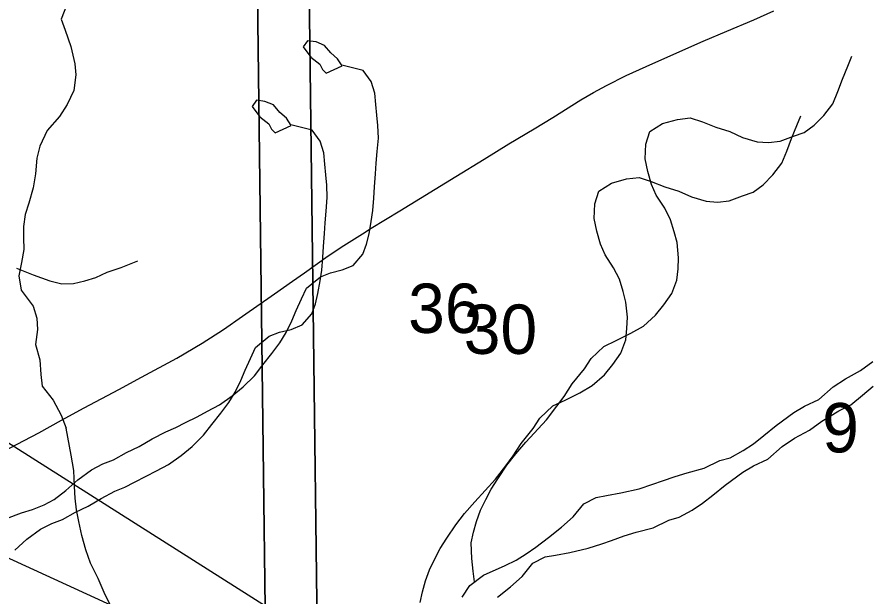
# Model space of a CAD drawing. Extents: x -21.1 to 50.3, y -4.9 to 22.1.
# Drawn here: x 4.587 to 5.308, y 17.38 to 17.871 of the extents above; entities that cross this region are included whole.
import ezdxf

# ---------------------------------------------------------------- set-up
doc = ezdxf.new("R2010")
doc.units = 0
for name, color, linetype in [('GM_X_Minor_Lake', 7, 'Continuous'), ('GM_X_Minor_River', 7, 'Continuous'), ('GM_X_Section', 7, 'Continuous'), ('GM_X_Section_Text', 7, 'Continuous'), ('GM_X_Township_Road', 7, 'Continuous'), ('SH_Data', 7, 'Continuous')]:
    doc.layers.add(name, color=color, linetype=linetype)

msp = doc.modelspace()

# ---------------------------------------------------------------- linework, layer by layer
at = {"layer": 'GM_X_Minor_Lake'}
for points in [[(4.86329, 17.82987), (4.85943, 17.8359), (4.85369, 17.84077), (4.84831, 17.84717), (4.84107, 17.85013), (4.83385, 17.85119), (4.83012, 17.84583), (4.83666, 17.83718), (4.84431, 17.83119), (4.84664, 17.82666), (4.84971, 17.82366)], [(4.84971, 17.82366), (4.86329, 17.82987)], [(4.82, 17.77936), (4.81614, 17.78539), (4.8104, 17.79026), (4.80502, 17.79665), (4.79778, 17.79961), (4.79056, 17.80067), (4.78683, 17.79532), (4.79337, 17.78666), (4.80102, 17.78067), (4.80335, 17.77614), (4.80642, 17.77314)], [(4.80642, 17.77314), (4.82, 17.77936)]]:
    msp.add_lwpolyline(points, dxfattribs=at)
at = {"layer": 'GM_X_Minor_River'}
for points in [[(4.63015, 17.88241), (4.62483, 17.86952), (4.62824, 17.86004), (4.63316, 17.84638), (4.63656, 17.83159), (4.63732, 17.82211), (4.63579, 17.80883), (4.6301, 17.79708), (4.62365, 17.78684), (4.61303, 17.77508), (4.60696, 17.7618), (4.6043, 17.75156), (4.60315, 17.73829), (4.60125, 17.72653), (4.59746, 17.71326), (4.59442, 17.70377), (4.5929, 17.69353), (4.59289, 17.68405), (4.59327, 17.67419), (4.59136, 17.66319), (4.58908, 17.65181), (4.59097, 17.63968), (4.6012, 17.62603), (4.60423, 17.61579), (4.60498, 17.6063), (4.60308, 17.59341), (4.60686, 17.58051), (4.60761, 17.568), (4.60875, 17.55814), (4.61822, 17.54638), (4.62504, 17.53349), (4.6292, 17.52249)], [(4.9756, 17.39228), (4.97444, 17.40135), (4.97323, 17.41198), (4.97278, 17.42528), (4.97463, 17.4344), (4.97724, 17.44354), (4.98062, 17.45305), (4.98513, 17.4622), (4.98965, 17.47096), (4.99531, 17.47973), (5.00286, 17.49116), (5.01042, 17.5007), (5.01912, 17.51063), (5.03652, 17.52972), (5.04521, 17.54116), (5.05164, 17.54955), (5.05843, 17.56023), (5.06863, 17.57282), (5.07429, 17.58159), (5.08527, 17.59191), (5.09552, 17.5969), (5.10805, 17.60305), (5.11868, 17.60919), (5.1289, 17.61836), (5.13608, 17.62714), (5.14288, 17.63667), (5.147, 17.64809), (5.14809, 17.65759), (5.14842, 17.66709), (5.14721, 17.68), (5.14487, 17.6891), (5.14177, 17.69934), (5.13676, 17.7092), (5.12947, 17.72017), (5.12561, 17.72927), (5.12251, 17.74026), (5.12016, 17.75089), (5.12085, 17.76343), (5.12422, 17.77408), (5.13484, 17.78098), (5.14776, 17.78447), (5.15841, 17.78567), (5.16871, 17.7823), (5.18015, 17.77781), (5.19197, 17.77408), (5.20266, 17.7692), (5.21524, 17.76547), (5.22476, 17.76476), (5.23465, 17.76596), (5.24605, 17.7702), (5.25517, 17.77329), (5.26351, 17.77941), (5.27183, 17.78782), (5.27939, 17.79773), (5.28352, 17.80801), (5.28765, 17.81867), (5.29215, 17.82971), (5.29553, 17.83809)], [(4.5787, 17.44588), (4.59123, 17.45089), (4.60073, 17.4536), (4.61061, 17.45746), (4.61896, 17.46206), (4.62881, 17.46971), (4.63904, 17.47889), (4.65079, 17.48731), (4.66028, 17.4923), (4.66939, 17.49577), (4.6804, 17.50191), (4.69103, 17.50691), (4.70203, 17.51343), (4.71379, 17.51957), (4.72215, 17.52304), (4.7305, 17.52726), (4.74037, 17.53225), (4.7491, 17.53686), (4.75934, 17.54224), (4.76996, 17.54989), (4.77943, 17.55754), (4.78889, 17.56709), (4.79607, 17.57625), (4.80363, 17.58579), (4.81043, 17.59494), (4.81571, 17.60371), (4.82061, 17.61361), (4.82436, 17.62237), (4.82888, 17.63227), (4.83301, 17.64141), (4.84476, 17.65097), (4.85349, 17.65444), (4.86338, 17.65677), (4.87249, 17.66063), (4.88081, 17.67017), (4.88381, 17.67854), (4.88604, 17.68729), (4.88789, 17.69794), (4.88936, 17.70706), (4.89006, 17.7177), (4.89077, 17.7272), (4.89147, 17.73822), (4.89218, 17.74734), (4.89288, 17.75723), (4.89396, 17.76863), (4.89352, 17.77926), (4.89271, 17.78799), (4.8919, 17.79711), (4.89108, 17.8066), (4.88798, 17.81646), (4.88108, 17.82592), (4.86298, 17.83035)], [(4.92949, 17.37476), (4.93134, 17.38389), (4.93395, 17.39302), (4.93733, 17.40254), (4.94185, 17.41168), (4.94636, 17.42044), (4.95202, 17.42921), (4.95957, 17.44065), (4.96713, 17.45018), (4.97583, 17.46011), (4.99323, 17.4792), (5.00192, 17.49065), (5.00835, 17.49904), (5.01514, 17.50971), (5.02535, 17.52231), (5.03101, 17.53107), (5.04199, 17.54139), (5.05224, 17.54639), (5.06476, 17.55254), (5.07539, 17.55867), (5.08561, 17.56784), (5.09279, 17.57662), (5.09959, 17.58615), (5.10371, 17.59757), (5.1048, 17.60708), (5.10513, 17.61658), (5.10392, 17.62949), (5.10158, 17.63859), (5.09848, 17.64883), (5.09348, 17.65868), (5.08618, 17.66965), (5.08232, 17.67875), (5.07922, 17.68975), (5.07687, 17.70037), (5.07756, 17.71291), (5.08093, 17.72357), (5.09155, 17.73046), (5.10447, 17.73395), (5.11512, 17.73515), (5.12542, 17.73179), (5.13686, 17.72729), (5.14868, 17.72356), (5.15937, 17.71868), (5.17195, 17.71495), (5.18147, 17.71425), (5.19136, 17.71544), (5.20276, 17.71968), (5.21188, 17.72277), (5.22022, 17.7289), (5.22854, 17.7373), (5.2361, 17.74722), (5.24023, 17.7575), (5.24436, 17.76816), (5.24886, 17.7792), (5.25224, 17.78757)], [(4.58552, 17.4192), (4.59575, 17.42837), (4.6075, 17.43679), (4.61699, 17.44179), (4.6261, 17.44525), (4.63711, 17.45139), (4.64774, 17.45639), (4.65874, 17.46291), (4.6705, 17.46905), (4.67886, 17.47252), (4.68721, 17.47674), (4.69708, 17.48174), (4.70581, 17.48634), (4.71605, 17.49172), (4.72667, 17.49938), (4.73614, 17.50703), (4.7456, 17.51657), (4.75278, 17.52573), (4.76035, 17.53527), (4.76715, 17.54443), (4.77242, 17.55319), (4.77732, 17.5631), (4.78108, 17.57186), (4.78559, 17.58175), (4.78972, 17.5909), (4.80147, 17.60046), (4.8102, 17.60392), (4.82009, 17.60626), (4.8292, 17.61011), (4.83752, 17.61965), (4.84052, 17.62803), (4.84275, 17.63678), (4.8446, 17.64742), (4.84607, 17.65655), (4.84677, 17.66719), (4.84748, 17.67669), (4.84818, 17.68771), (4.84889, 17.69683), (4.84959, 17.70671), (4.85067, 17.71811), (4.85023, 17.72875), (4.84942, 17.73748), (4.84861, 17.74659), (4.84779, 17.75608), (4.84469, 17.76594), (4.83779, 17.7754), (4.8197, 17.77983)], [(4.58694, 17.65819), (4.60129, 17.65265), (4.61526, 17.6475), (4.62548, 17.64506), (4.63536, 17.64529), (4.64489, 17.64743), (4.65443, 17.65033), (4.66399, 17.65474), (4.67583, 17.65874), (4.68997, 17.6646)], [(4.96504, 17.37927), (4.97146, 17.38918), (4.98321, 17.39798), (5.00144, 17.40606), (5.01093, 17.41067), (5.01927, 17.41604), (5.02761, 17.42178), (5.03822, 17.42982), (5.04922, 17.43862), (5.05906, 17.44741), (5.06813, 17.45848), (5.07876, 17.46385), (5.08751, 17.46542), (5.09968, 17.46777), (5.11526, 17.47127), (5.12666, 17.47513), (5.13502, 17.47784), (5.14565, 17.4817), (5.15591, 17.48479), (5.17036, 17.48867), (5.18364, 17.4952), (5.19239, 17.49753), (5.20339, 17.50367), (5.21211, 17.50942), (5.22083, 17.5163), (5.23144, 17.52472), (5.24622, 17.53582), (5.25533, 17.54119), (5.26747, 17.54695), (5.2796, 17.55765), (5.29022, 17.56455), (5.30274, 17.57146), (5.31335, 17.57911)], [(4.99494, 17.3793), (5.00593, 17.3881), (5.01577, 17.39689), (5.02485, 17.40796), (5.03547, 17.41334), (5.04422, 17.4149), (5.05639, 17.41725), (5.07197, 17.42076), (5.08337, 17.42462), (5.09173, 17.42732), (5.10237, 17.43118), (5.11263, 17.43428), (5.12707, 17.43816), (5.14035, 17.44469), (5.1491, 17.44702), (5.1601, 17.45315), (5.16882, 17.4589), (5.17754, 17.46579), (5.18815, 17.4742), (5.20293, 17.4853), (5.21204, 17.49067), (5.22419, 17.49643), (5.23631, 17.50714), (5.24693, 17.51404), (5.25945, 17.52094), (5.27006, 17.5286), (5.28448, 17.53742), (5.29473, 17.54241), (5.30458, 17.55044), (5.31367, 17.55809)], [(4.66671, 17.37228), (4.66147, 17.38331), (4.65624, 17.39511), (4.64987, 17.40804), (4.64577, 17.41945), (4.64243, 17.43161), (4.63986, 17.44339), (4.63802, 17.45327), (4.63695, 17.46314), (4.63625, 17.47301), (4.63558, 17.48667), (4.63339, 17.49958), (4.6292, 17.52249)]]:
    msp.add_lwpolyline(points, dxfattribs=at)
at = {"layer": 'GM_X_Section'}
for points in [[(3.80452, 18.01477), (4.83425, 17.98542), (4.84683, 16.96859), (4.43354, 16.98495), (3.82173, 16.99041)], [(5.81893, 17.99203), (5.83147, 16.97938), (4.84683, 16.96859), (4.83425, 17.98542)], [(3.76124, 17.96425), (4.79096, 17.9349), (4.80354, 16.91807), (4.39025, 16.93443), (3.77844, 16.93989)], [(5.77564, 17.94152), (5.78818, 16.92886), (4.80354, 16.91807), (4.79096, 17.9349)]]:
    msp.add_lwpolyline(points, close=True, dxfattribs=at)
at = {"layer": 'GM_X_Township_Road'}
for points in [[(4.88043, 17.6875), (4.88794, 17.69217), (4.91204, 17.70676), (4.95972, 17.73595), (4.98355, 17.7506), (5.00468, 17.76373), (5.0261, 17.77642), (5.04203, 17.78608), (5.06573, 17.80089), (5.07643, 17.80725), (5.08735, 17.81327), (5.1041, 17.82153), (5.1267, 17.83194), (5.16933, 17.85089), (5.18939, 17.85938), (5.21232, 17.86899), (5.22938, 17.87653)], [(4.51792, 17.47181), (4.53137, 17.47952), (4.54592, 17.48714), (4.58102, 17.50567), (4.60598, 17.5187), (4.62515, 17.52925), (4.6444, 17.5398), (4.67397, 17.5554), (4.69299, 17.56584), (4.72291, 17.58203), (4.74444, 17.59463), (4.76272, 17.60628), (4.77879, 17.61745), (4.80578, 17.63645), (4.8212, 17.64721), (4.83138, 17.65435), (4.85132, 17.66871), (4.86458, 17.67762), (4.88043, 17.6875)]]:
    msp.add_lwpolyline(points, dxfattribs=at)
at = {"layer": 'SH_Data'}
msp.add_lwpolyline([(3.93924, 17.70664), (5.13599, 17.1573), (3.93924, 17.91664)], close=True, dxfattribs=at)

# ---------------------------------------------------------------- texts
at = {"layer": 'GM_X_Section_Text'}
for s, height, p in [('36', 0.041856, (4.91919, 17.60331)), ('30', 0.041856, (4.96637, 17.58557)), ('9', 0.04186, (5.27031, 17.50203))]:
    msp.add_text(s, height=height, rotation=0.00001, dxfattribs=at).set_placement(p)

doc.saveas('drawing.dxf')
